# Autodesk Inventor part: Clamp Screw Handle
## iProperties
Created: 2002-02
Part Number: Clamp Screw Handle
Document SubType Name: Modeling
Designer: ***
Control State: 0
Master: False
Checked Out: False
Shininess: 77.0
Length Units: 11269
Angle Units: 11279
Time Units: 11290
Mass Units: 11283
Length Display Precision: 3
Angle Display Precision: 2
Compacted: True
Density: 0.0
Volumn: 0.0
Area: 0.0
PropertySet Name: Model Information
Author: ***
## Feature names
1. Revolution1
